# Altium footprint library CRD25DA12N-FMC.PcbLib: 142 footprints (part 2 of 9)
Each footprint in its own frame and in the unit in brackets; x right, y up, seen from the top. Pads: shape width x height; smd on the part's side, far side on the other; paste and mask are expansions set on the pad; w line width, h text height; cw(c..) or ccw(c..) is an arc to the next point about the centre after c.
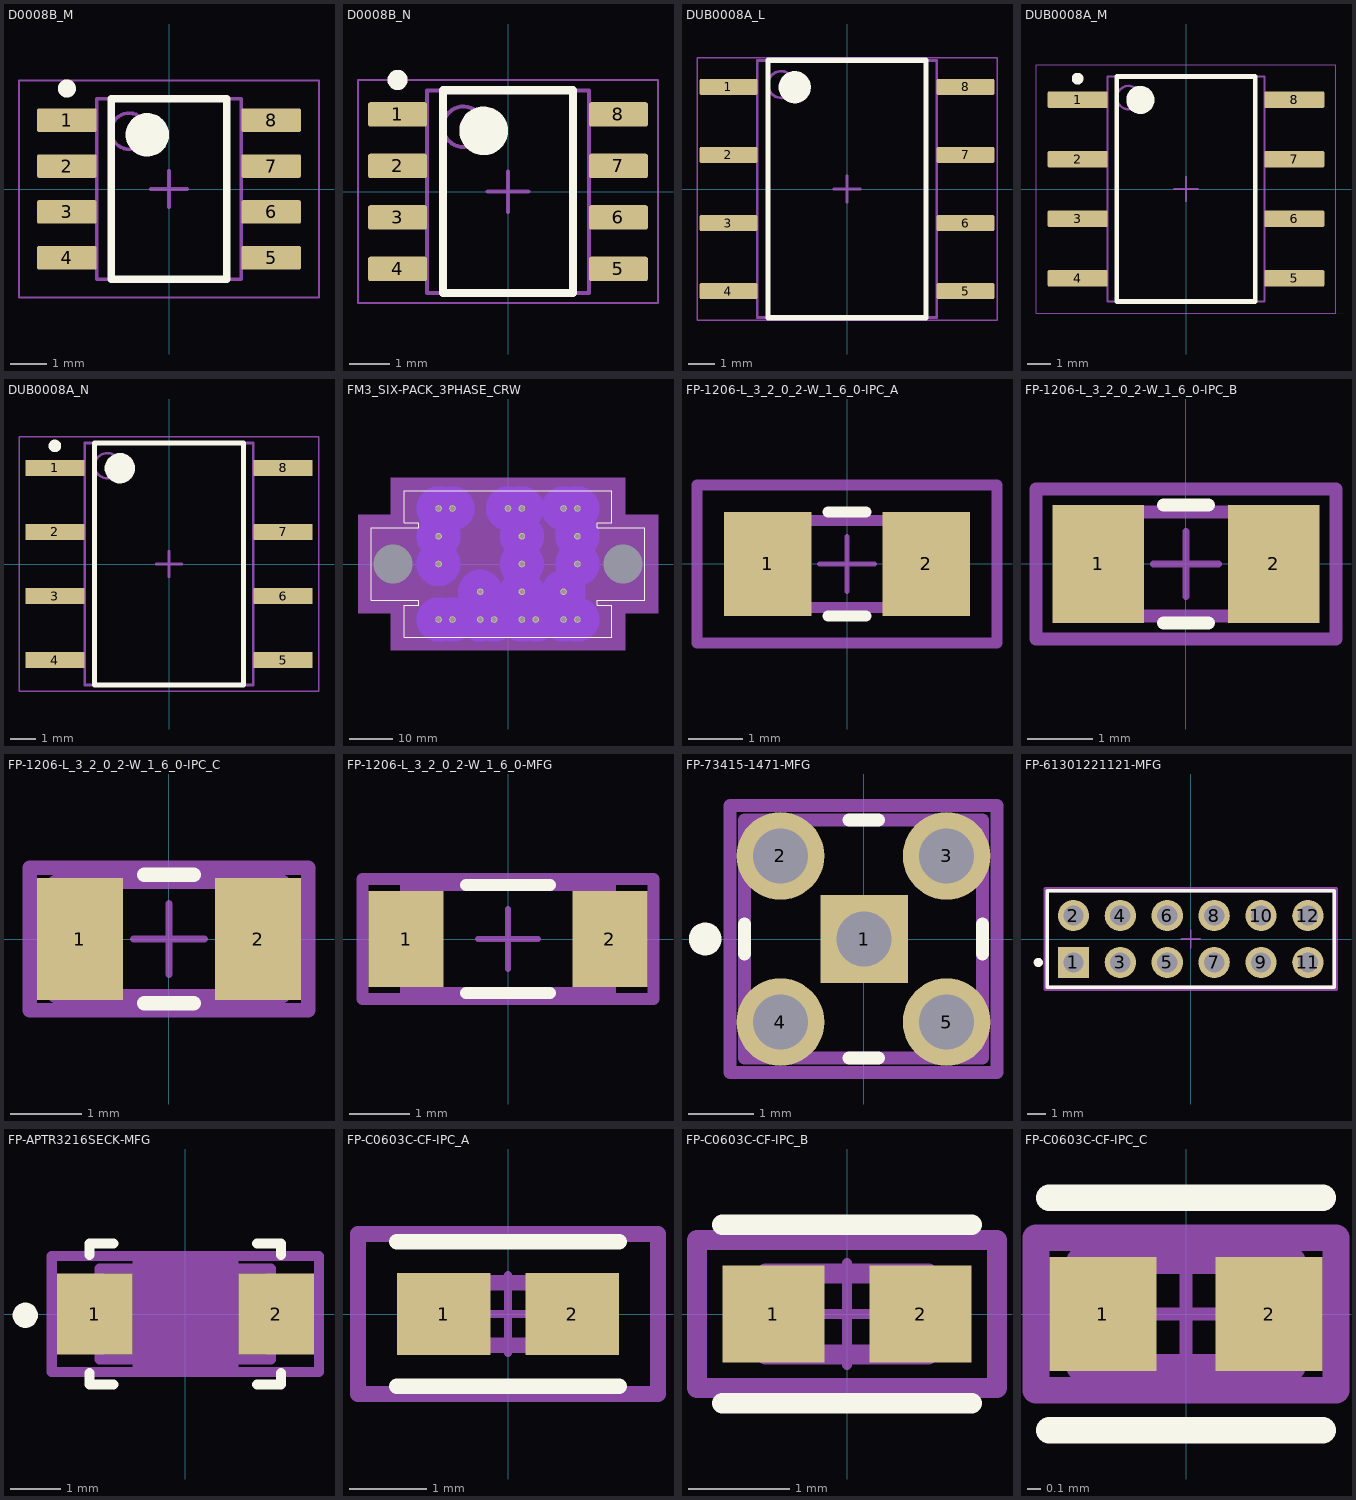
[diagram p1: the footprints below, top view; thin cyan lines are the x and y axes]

## D0008B_M [mm] "SOIC, 8-Leads, Body 5x4mm, Pitch 1.27mm, IPC Low Density"
height 1.75
pads (8):
  rrect15% 1.65x0.65 smd: 1(-2.825,1.905) 2(-2.825,0.635) 3(-2.825,-0.635) 4(-2.825,-1.905) 5(2.825,-1.905) 6(2.825,-0.635) 7(2.825,0.635) 8(2.825,1.905)
Top Overlay:
  circle w0.6: c-0.6,1.5 r0.3
  circle w0.25: c-2.825,2.78 r0.125
  lines w0.2: -1.6,-2.5 1.6,-2.5 1.6,2.5 -1.6,2.5 -1.6,-2.5
Mechanical 1:
  text ".Designator" at -1.397,-0.254 h0.6
Mechanical 13:
  circle w0.1: c-1.1,1.6 r0.5
  lines w0.1: -2,-2.5 2,-2.5 2,2.5 -2,2.5 -2,-2.5
Mechanical 15:
  lines w0.05: -4.15,-3 4.15,-3 4.15,3 -4.15,3 -4.15,-3
  lines w0.1: -0.5,0 0.5,0 ; 0,-0.5 0,0.5
3D body "SOIC-8akaD0008AakaM08A.stp": height 1.63, standoff 0, extent -3,-2.45 3,2.45

## D0008B_N [mm] "SOIC, 8-Leads, Body 5x4mm, Pitch 1.27mm, IPC Medium Density"
height 1.75
pads (8):
  rrect17% 1.45x0.6 smd: 1(-2.725,1.905) 2(-2.725,0.635) 3(-2.725,-0.635) 4(-2.725,-1.905) 5(2.725,-1.905) 6(2.725,-0.635) 7(2.725,0.635) 8(2.725,1.905)
Top Overlay:
  circle w0.6: c-0.6,1.5 r0.3
  circle w0.25: c-2.725,2.755 r0.125
  lines w0.2: -1.6,-2.5 1.6,-2.5 1.6,2.5 -1.6,2.5 -1.6,-2.5
Mechanical 1:
  text ".Designator" at -1.397,-0.254 h0.6
Mechanical 13:
  circle w0.1: c-1.1,1.6 r0.5
  lines w0.1: -2,-2.5 2,-2.5 2,2.5 -2,2.5 -2,-2.5
Mechanical 15:
  lines w0.05: -3.7,-2.75 3.7,-2.75 3.7,2.75 -3.7,2.75 -3.7,-2.75
  lines w0.1: -0.5,0 0.5,0 ; 0,-0.5 0,0.5
3D body "SOIC-8akaD0008AakaM08A.stp": height 1.63, standoff 0, extent -3,-2.45 3,2.45

## DUB0008A_L [mm] "SOP, 8-Leads, Body 6.7x9.6mm, Pitch 2.54mm, IPC High Density"
height 4.85
pads (8):
  rrect17% 2.15x0.6 smd: 1(-4.425,3.81) 2(-4.425,1.27) 3(-4.425,-1.27) 4(-4.425,-3.81) 5(4.425,-3.81) 6(4.425,-1.27) 7(4.425,1.27) 8(4.425,3.81)
Top Overlay:
  circle w0.6: c-1.95,3.8 r0.3
  lines w0.2: -2.95,-4.8 -2.95,4.8 2.95,4.8 2.95,-4.8 -2.95,-4.8
Mechanical 1:
  text ".Designator" at -2.286,-0.381 h1
Mechanical 13:
  circle w0.1: c-2.45,3.9 r0.5
  lines w0.1: -3.35,-4.8 -3.35,4.8 3.35,4.8 3.35,-4.8 -3.35,-4.8
Mechanical 15:
  lines w0.05: -5.6,-4.9 -5.6,4.9 5.6,4.9 5.6,-4.9 -5.6,-4.9
  lines w0.1: -0.5,0 0.5,0 ; 0,-0.5 0,0.5
3D body "DUB0008A.stp": height 4.85, standoff 0, extent -5.242,-4.75 5.242,4.75

## DUB0008A_M [mm] "SOP, 8-Leads, Body 6.7x9.6mm, Pitch 2.54mm, IPC Low Density"
height 4.85
pads (8):
  rrect14% 2.55x0.7 smd: 1(-4.625,3.81) 2(-4.625,1.27) 3(-4.625,-1.27) 4(-4.625,-3.81) 5(4.625,-3.81) 6(4.625,-1.27) 7(4.625,1.27) 8(4.625,3.81)
Top Overlay:
  circle w0.6: c-1.95,3.8 r0.3
  circle w0.25: c-4.625,4.71 r0.125
  lines w0.2: -2.95,-4.8 2.95,-4.8 2.95,4.8 -2.95,4.8 -2.95,-4.8
Mechanical 1:
  text ".Designator" at -2.286,-0.254 h1
Mechanical 13:
  circle w0.1: c-2.45,3.9 r0.5
  lines w0.1: -3.35,-4.8 3.35,-4.8 3.35,4.8 -3.35,4.8 -3.35,-4.8
Mechanical 15:
  lines w0.05: -6.4,-5.3 6.4,-5.3 6.4,5.3 -6.4,5.3 -6.4,-5.3
  lines w0.1: -0.5,0 0.5,0 ; 0,-0.5 0,0.5
3D body "DUB0008A.stp": height 4.85, standoff 0, extent -5.242,-4.75 5.242,4.75

## DUB0008A_N [mm] "SOP, 8-Leads, Body 6.7x9.6mm, Pitch 2.54mm, IPC Medium Density"
height 4.85
pads (8):
  rrect15% 2.35x0.65 smd: 1(-4.525,3.81) 2(-4.525,1.27) 3(-4.525,-1.27) 4(-4.525,-3.81) 5(4.525,-3.81) 6(4.525,-1.27) 7(4.525,1.27) 8(4.525,3.81)
Top Overlay:
  circle w0.25: c-4.525,4.685 r0.125
  circle w0.6: c-1.95,3.8 r0.3
  lines w0.2: -2.95,-4.8 -2.95,4.8 2.95,4.8 2.95,-4.8 -2.95,-4.8
Mechanical 1:
  text ".Designator" at -2.54,-0.254 h1
Mechanical 13:
  circle w0.1: c-2.45,3.9 r0.5
  lines w0.1: -3.35,-4.8 -3.35,4.8 3.35,4.8 3.35,-4.8 -3.35,-4.8
Mechanical 15:
  lines w0.05: -5.95,-5.05 -5.95,5.05 5.95,5.05 5.95,-5.05 -5.95,-5.05
  lines w0.1: -0.5,0 0.5,0 ; 0,-0.5 0,0.5
3D body "DUB0008A.stp": height 4.85, standoff 0, extent -5.242,-4.75 5.242,4.75

## FM3_SIX-PACK_3PHASE_CRW [mm]
pads (25):
  round 1.524 hole 1.1: DC+_1(-6.4,-6.4) DC+_2(3.2,-6.4) DC+_3(12.8,-6.4) DC-1(-16,0) DC-2(3.2,0) DC-3(16,0) G1(-12.8,-12.8) G2(-16,12.8) G3(-3.2,-12.8) G4(3.2,12.8) G5(6.4,-12.8) G6(16,12.8) NTC1(12.8,-12.8) NTC2(16,-12.8) S1(-16,-12.8) S2(-12.8,12.8) S3(-6.4,-12.8) S4(0,12.8) S5(3.2,-12.8) S6(12.8,12.8) U(-16,6.4) V(3.2,6.4) W(16,6.4)
  round 0 hole 9 unplated: MH1(-26.5,0) MH2(26.5,0)
Bottom Layer keep-out:
  circle w6.2: c3.2,0 r2
  circle w6.2: c3.2,6.4 r2
  circle w6.2: c16,6.4 r2
  circle w6.2: c16,0 r2
  circle w6.2: c12.8,-6.4 r2
  circle w6.2: c3.2,-6.4 r2
  circle w6.2: c-6.4,-6.4 r2
  circle w6.2: c-16,0 r2
  circle w6.2: c-16,6.4 r2
  circle w6.2: c-16,-12.8 r2
  circle w6.2: c-12.8,-12.8 r2
  circle w6.2: c-6.4,-12.8 r2
  circle w6.2: c-3.2,-12.8 r2
  circle w6.2: c3.2,-12.8 r2
  circle w6.2: c6.4,-12.8 r2
  circle w6.2: c12.8,-12.8 r2
  circle w6.2: c16,-12.8 r2
  circle w6.2: c3.2,12.8 r2
  circle w6.2: c12.8,12.8 r2
  circle w6.2: c0,12.8 r2
  circle w6.2: c-12.8,12.8 r2
  circle w6.2: c-16,12.8 r2
  circle w6.2: c16,12.8 r2
Top Overlay:
  lines w0.152: -31.521,-8.331 -31.521,8.331 -20.625,8.331 -20.625,9.563 -23.927,9.563 -23.927,16.878 23.927,16.878 23.927,9.563 20.625,9.563 20.625,8.331 31.521,8.331 31.521,-8.331 20.625,-8.331 20.625,-9.563 23.927,-9.563 23.927,-16.878 -23.927,-16.878 -23.927,-9.563 -20.625,-9.563 -20.625,-8.331 -31.521,-8.331
Bottom Courtyard:
  text "Default Padstyle: EX60Y60D43P0" at -9.525,-21.831 h1.27
Bottom 3D Body:
  region: 26.975,19.926 -26.975,19.926 -26.975,11.379 -34.569,11.379 -34.569,-11.379 -26.975,-11.379 -26.975,-19.926 26.975,-19.926 26.975,-11.379 34.569,-11.379 34.569,11.379 26.975,11.379
Top Designator:
  text ".Designator" at 7.618,-0.694 h1.52
Mechanical 13:
  drawing of 27 lines, arcs and shapes, not listed
Mechanical 15:
  region: 20.752,-9.436 20.752,-8.458 31.648,-8.458 31.648,8.458 20.752,8.458 20.752,9.436 24.054,9.436 24.054,17.005 -24.054,17.005 -24.054,9.436 -20.752,9.436 -20.752,8.458 -31.648,8.458 -31.648,-8.458 -20.752,-8.458 -20.752,-9.436 -24.054,-9.436 -24.054,-17.005 24.054,-17.005 24.054,-9.436
  lines w0.152: -31.648,-8.458 -31.648,8.458 -20.752,8.458 -20.752,9.436 -24.054,9.436 -24.054,17.005 24.054,17.005 24.054,9.436 20.752,9.436 20.752,8.458 31.648,8.458 31.648,-8.458 20.752,-8.458 20.752,-9.436 24.054,-9.436 24.054,-17.005 -24.054,-17.005 -24.054,-9.436 -20.752,-9.436 -20.752,-8.458 -31.648,-8.458
3D body "McMaster-Carr 93070A095 - Alternative.STEP": height -7.7, standoff -16.5, extent -30,-3.5 -23,3.5
3D body "McMaster-Carr 93070A095 - Alternative.STEP": height -7.7, standoff -16.5, extent 23,-3.5 30,3.5
3D body: height 0.25, standoff 0, extent 0,0 0.254,0.254
3D body "CCB0xxM12FM3(Six_Pack)_External_POD_20200723_Branded_Origin.STEP": height 11.98, standoff -4.42, extent -31.4,-16.9 31.4,16.9

## FP-1206-L_3_2_0_2-W_1_6_0-IPC_A [mm]
pads (2):
  rect 1.604x1.906 smd paste+0 mask+0: 1(-1.451,0) 2(1.451,0)
Top Overlay:
  lines w0.2: -0.349,-0.953 0.349,-0.953 ; -0.349,0.953 0.349,0.953
Mechanical 5:
  lines w0.2: -2.753,-1.453 2.753,-1.453 2.753,1.453 -2.753,1.453 -2.753,-1.453
  text ".Designator" at 0,0.188 h1
Mechanical 13:
  lines w0.2: -1.6,-0.8 1.6,-0.8 1.6,0.8 -1.6,0.8 -1.6,-0.8
Mechanical 15:
  lines w0.2: -2.753,-1.453 2.753,-1.453 2.753,1.453 -2.753,1.453 -2.753,-1.453
Mechanical 16:
  lines w0.1: -0.5,0 0.5,0 ; 0,-0.5 0,0.5
3D body "Cap_Taiyo_Yuden_JMK316ABJ226KLHT_eec.STEP": height 0.25, standoff 0, extent -2.753,-1.453 2.753,1.453

## FP-1206-L_3_2_0_2-W_1_6_0-IPC_B [mm]
pads (2):
  rect 1.404x1.806 smd paste+0 mask+0: 1(-1.351,0) 2(1.351,0)
Top Overlay:
  lines w0.2: -0.349,-0.903 0.349,-0.903 ; -0.349,0.903 0.349,0.903
Mechanical 5:
  lines w0.2: -2.303,-1.153 2.303,-1.153 2.303,1.153 -2.303,1.153 -2.303,-1.153
  text ".Designator" at 0,0.188 h1
Mechanical 13:
  lines w0.2: -1.6,-0.8 1.6,-0.8 1.6,0.8 -1.6,0.8 -1.6,-0.8
Mechanical 15:
  lines w0.2: -2.303,-1.153 2.303,-1.153 2.303,1.153 -2.303,1.153 -2.303,-1.153
Mechanical 16:
  lines w0.1: -0.5,0 0.5,0 ; 0,-0.5 0,0.5
3D body "Cap_Taiyo_Yuden_JMK316ABJ226KLHT_eec.STEP": height 0.25, standoff 0, extent -2.303,-1.153 2.303,1.153

## FP-1206-L_3_2_0_2-W_1_6_0-IPC_C [mm]
pads (2):
  rect 1.204x1.706 smd paste+0 mask+0: 1(-1.251,0) 2(1.251,0)
Top Overlay:
  lines w0.2: -0.349,-0.9 0.349,-0.9 ; -0.349,0.9 0.349,0.9
Mechanical 5:
  lines w0.2: -1.953,-1 1.953,-1 1.953,1 -1.953,1 -1.953,-1
  text ".Designator" at 0,0.188 h1
Mechanical 13:
  lines w0.2: -1.6,-0.8 1.6,-0.8 1.6,0.8 -1.6,0.8 -1.6,-0.8
Mechanical 15:
  lines w0.2: -1.953,-1 1.953,-1 1.953,1 -1.953,1 -1.953,-1
Mechanical 16:
  lines w0.1: -0.5,0 0.5,0 ; 0,-0.5 0,0.5
3D body "Cap_Taiyo_Yuden_JMK316ABJ226KLHT_eec.STEP": height 0.25, standoff 0, extent -1.953,-1 1.953,1

## FP-1206-L_3_2_0_2-W_1_6_0-MFG [mm]
pads (2):
  rect 1.25x1.6 smd paste+0 mask+0: 1(-1.7,0) 2(1.7,0)
Top Overlay:
  lines w0.2: -0.7,-0.9 0.7,-0.9 ; -0.7,0.9 0.7,0.9
Mechanical 5:
  lines w0.2: -2.425,-1 -2.425,1 2.425,1 2.425,-1 -2.425,-1
  text ".Designator" at 0,0.188 h1
Mechanical 13:
  lines w0.2: -1.7,-0.9 -1.7,0.9 1.7,0.9 1.7,-0.9 -1.7,-0.9
Mechanical 15:
  lines w0.2: -2.425,-1 -2.425,1 2.425,1 2.425,-1 -2.425,-1
Mechanical 16:
  lines w0.1: -0.5,0 0.5,0 ; 0,-0.5 0,0.5
3D body "Cap_Taiyo_Yuden_JMK316ABJ226KLHT_eec.STEP": height 0.25, standoff 0, extent -2.425,-1 2.425,1

## FP-73415-1471-MFG [mm]
pads (5):
  rect 1.34x1.34 hole 0.84 paste-2539.97 mask+0: 1(0.01,0)
  round 1.34 hole 0.84 paste-2539.97 mask+0: 2(-1.27,1.27) 3(1.27,1.27) 4(-1.27,-1.27) 5(1.27,-1.27)
Top Overlay:
  circle w0.25: c-2.42,0 r0.125
  lines w0.2: -1.82,-0.225 -1.82,0.225 ; -0.225,-1.82 0.225,-1.82 ; -0.225,1.82 0.225,1.82 ; 1.82,-0.225 1.82,0.225
Mechanical 5:
  lines w0.2: -2.04,-2.04 -2.04,2.04 2.04,2.04 2.04,-2.04 -2.04,-2.04
  text ".Designator" at 0,0.188 h1
Mechanical 13:
  lines w0.2: -1.82,-1.82 -1.82,1.82 1.82,1.82 1.82,-1.82 -1.82,-1.82
Mechanical 15:
  lines w0.2: -2.04,-2.04 -2.04,2.04 2.04,2.04 2.04,-2.04 -2.04,-2.04
Mechanical 16:
  lines w0.1: -0.5,0 0.5,0 ; 0,-0.5 0,0.5
3D body "Conn_Molex_73415-1471_eec.STEP": height 0.25, standoff 0, extent -2.04,-2.04 2.04,2.04

## FP-61301221121-MFG [mm]
pads (12):
  rect 1.7x1.7 hole 1.1 paste-2539.97 mask+0: 1(-6.35,-1.27)
  round 1.7 hole 1.1 paste-2539.97 mask+0: 2(-6.35,1.27) 3(-3.81,-1.27) 4(-3.81,1.27) 5(-1.27,-1.27) 6(-1.27,1.27) 7(1.27,-1.27) 8(1.27,1.27) 9(3.81,-1.27) 10(3.81,1.27) 11(6.35,-1.27) 12(6.35,1.27)
Top Overlay:
  circle w0.25: c-8.255,-1.27 r0.125
  lines w0.2: -7.77,-2.615 7.77,-2.615 7.77,2.615 -7.77,2.615 -7.77,-2.615
Mechanical 5:
  lines w0.2: -7.87,-2.715 7.87,-2.715 7.87,2.715 -7.87,2.715 -7.87,-2.715
  text ".Designator" at 0,0.188 h1
Mechanical 13:
  lines w0.2: -7.77,-2.615 7.77,-2.615 7.77,2.615 -7.77,2.615 -7.77,-2.615
Mechanical 15:
  lines w0.2: -7.87,-2.715 7.87,-2.715 7.87,2.715 -7.87,2.715 -7.87,-2.715
Mechanical 16:
  lines w0.1: -0.5,0 0.5,0 ; 0,-0.5 0,0.5
3D body "Conn_Wurth_Electronics_61301221121_eec.STEP": height 0.25, standoff 0, extent -7.87,-2.715 7.87,2.715

## FP-APTR3216SECK-MFG [mm]
pads (2):
  rect 1.5x1.6 smd paste+0 mask+0: 1(-1.8,0) 2(1.8,0)
Top Overlay:
  circle w0.25: c-3.175,-0.025 r0.125
  lines w0.2: -1.9,-1.175 -1.9,-1.4 -1.425,-1.4 ; -1.9,1.175 -1.9,1.4 -1.425,1.4 ; 1.425,-1.4 1.9,-1.4 1.9,-1.175 ; 1.425,1.4 1.9,1.4 1.9,1.175
Bottom 3D Body:
  rectangle: -1.05,-1.15 1.05,1.15
Mechanical 5:
  lines w0.2: -2.65,-1.15 -2.65,1.15 2.65,1.15 2.65,-1.15 -2.65,-1.15
  text ".Designator" at 0,0 h1
Mechanical 13:
  lines w0.2: -1.7,-0.9 -1.7,0.9 1.7,0.9 1.7,-0.9 -1.7,-0.9
Mechanical 15:
  lines w0.2: -2.65,-1.15 -2.65,1.15 2.65,1.15 2.65,-1.15 -2.65,-1.15
Mechanical 16:
  lines w0.1: -0.5,0 0.5,0 ; 0,-0.5 0,0.5
3D body "LED 1206 - PURPLE.STEP": height 1.1, standoff 0, extent -1.6,-0.8 1.6,0.802

## FP-C0603C-CF-IPC_A [mil]
pads (2):
  rect 47.5x41.66 smd paste+0 mask+0: 1(-32.51,0) 2(32.51,0)
Top Overlay:
  lines w7.87: -56.26,-36.58 56.26,-36.58 ; -56.26,36.58 56.26,36.58
Mechanical 5:
  lines w7.87: -75.95,-40.52 -75.95,40.52 75.95,40.52 75.95,-40.52 -75.95,-40.52
  text ".Designator" at 0,7.4 h39.37
Mechanical 13:
  lines w7.87: -31.5,-15.75 -31.5,15.75 31.5,15.75 31.5,-15.75 -31.5,-15.75
Mechanical 15:
  lines w7.87: -75.95,-40.52 -75.95,40.52 75.95,40.52 75.95,-40.52 -75.95,-40.52
Mechanical 16:
  lines w3.94: -19.68,0 19.68,0 ; 0,-19.68 0,19.68
3D body "Cap_KEMET_C0603C272M5JACTU_eec.STEP": height 10, standoff 0, extent -75.95,-40.52 75.95,40.52

## FP-C0603C-CF-IPC_B [mm]
pads (2):
  rect 1.007x0.958 smd paste+0 mask+0: 1(-0.726,0) 2(0.726,0)
Top Overlay:
  lines w0.2: -1.229,-0.879 1.229,-0.879 ; -1.229,0.879 1.229,0.879
Mechanical 5:
  lines w0.2: -1.479,-0.729 -1.479,0.729 1.479,0.729 1.479,-0.729 -1.479,-0.729
  text ".Designator" at 0,0.188 h1
Mechanical 13:
  lines w0.2: -0.8,-0.4 -0.8,0.4 0.8,0.4 0.8,-0.4 -0.8,-0.4
Mechanical 15:
  lines w0.2: -1.479,-0.729 -1.479,0.729 1.479,0.729 1.479,-0.729 -1.479,-0.729
Mechanical 16:
  lines w0.1: -0.5,0 0.5,0 ; 0,-0.5 0,0.5
3D body "Cap_KEMET_C0603C272M5JACTU_eec.STEP": height 0.25, standoff 0, extent -1.479,-0.729 1.479,0.729

## FP-C0603C-CF-IPC_C [mm]
pads (2):
  rect 0.807x0.858 smd paste+0 mask+0: 1(-0.626,0) 2(0.626,0)
Top Overlay:
  lines w0.2: -1.029,-0.875 1.029,-0.875 ; -1.029,0.875 1.029,0.875
Mechanical 5:
  lines w0.2: -1.129,-0.575 1.129,-0.575 1.129,0.575 -1.129,0.575 -1.129,-0.575
  text ".Designator" at 0,0.188 h1
Mechanical 13:
  lines w0.2: -0.8,-0.4 0.8,-0.4 0.8,0.4 -0.8,0.4 -0.8,-0.4
Mechanical 15:
  lines w0.2: -1.129,-0.575 1.129,-0.575 1.129,0.575 -1.129,0.575 -1.129,-0.575
Mechanical 16:
  lines w0.1: -0.5,0 0.5,0 ; 0,-0.5 0,0.5
3D body "Cap_KEMET_C0603C272M5JACTU_eec.STEP": height 0.25, standoff 0, extent -1.129,-0.575 1.129,0.575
